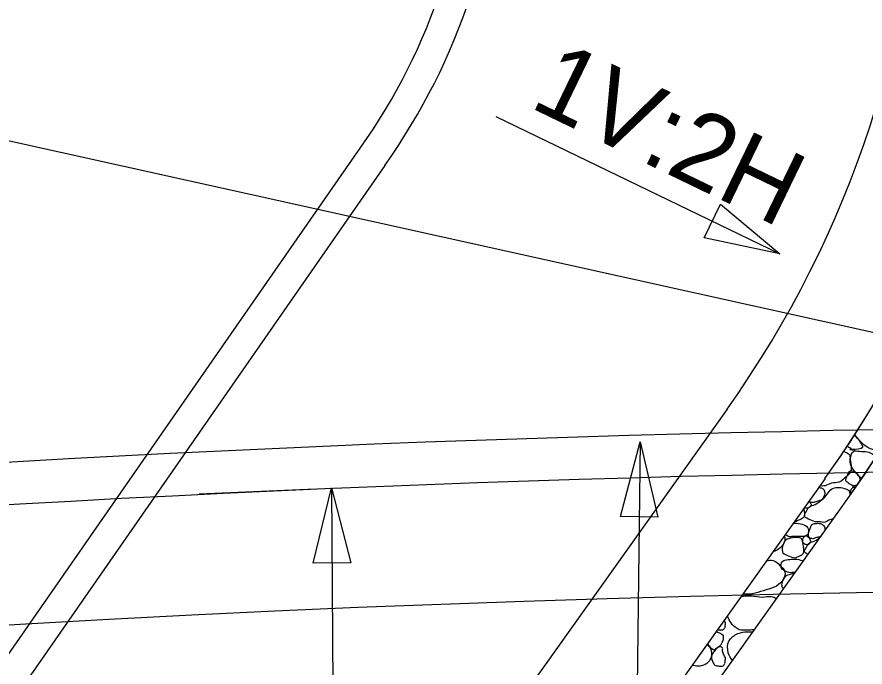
# Model space of a CAD drawing. Extents: x 1385284 to 1385995, y 1975154 to 1975620.
# Drawn here: x 1385473.66 to 1385501.91, y 1975497.97 to 1975519.64 of the extents above; entities that cross this region are included whole.
import ezdxf

# ---------------------------------------------------------------- set-up
doc = ezdxf.new("R2010")
doc.units = 0
for name, color, linetype in [('Default', 7, 'Continuous'), ('R_Bridge', 7, 'Continuous'), ('R_Horz Alg Annot', 7, 'Continuous'), ('R_Proposed Const Limits', 7, 'Continuous'), ('R_Proposed Road', 7, 'Continuous')]:
    doc.layers.add(name, color=color, linetype=linetype)

msp = doc.modelspace()

# ---------------------------------------------------------------- linework, layer by layer
at = {"layer": 'Default'}
for p, q in [((1385489.616, 1975516.319), (1385499.073, 1975511.745)), ((1385459.222, 1975478.038), (1385485.092, 1975515.258)), ((1385485.913, 1975514.687), (1385460.044, 1975477.467)), ((1385494.416, 1975505.475), (1385494.049, 1975472.644)), ((1385500.579, 1975504.251), (1385472.911, 1975465.371)), ((1385483.611, 1975503.895), (1385479.734, 1975503.734)), ((1385484.136, 1975503.942), (1385484.353, 1975473.943)), ((1385473.726, 1975464.791), (1385501.394, 1975503.671))]:
    msp.add_line(p, q, dxfattribs=at)
for points in [[(1385497.095, 1975513.396), (1385499.073, 1975511.745), (1385496.551, 1975512.271)], [(1385493.763, 1975502.983), (1385494.416, 1975505.475), (1385495.013, 1975502.969)], [(1385483.529, 1975501.438), (1385484.136, 1975503.942), (1385484.779, 1975501.447)]]:
    msp.add_lwpolyline(points, close=True, dxfattribs=at)
for radius, end in [(40, 101.9984), (39, 101.9984), (40, 46.1158), (39, 45.8751), (21, 101.9984), (20, 101.9984)]:
    msp.add_arc((1385468.803, 1975526.863), radius, 324.5634, end, dxfattribs=at)
for points in [[(1385501.542, 1975505.711), (1385501.59, 1975505.684), (1385501.684, 1975505.595), (1385501.749, 1975505.454), (1385501.936, 1975505.205), (1385501.187, 1975505.222), (1385501.573, 1975505.212), (1385501.565, 1975505.214)], [(1385502.213, 1975505.214), (1385502.142, 1975505.211), (1385501.96, 1975505.295), (1385501.763, 1975505.477), (1385501.628, 1975505.63), (1385501.558, 1975505.726), (1385501.555, 1975505.73)], [(1385501.175, 1975505.155), (1385501.185, 1975505.154), (1385501.247, 1975505.144), (1385501.42, 1975505.063), (1385501.412, 1975504.835), (1385501.498, 1975504.524), (1385501.284, 1975504.317), (1385501.062, 1975504.095), (1385500.786, 1975504.127), (1385500.577, 1975503.984), (1385500.459, 1975504.006), (1385500.409, 1975504.012)], [(1385501.531, 1975505.214), (1385501.484, 1975505.213), (1385501.404, 1975505.273), (1385501.326, 1975505.327), (1385501.304, 1975505.351)], [(1385501.783, 1975504.262), (1385501.783, 1975504.262), (1385501.703, 1975504.342), (1385501.552, 1975504.498), (1385501.394, 1975504.738), (1385501.426, 1975504.964), (1385501.497, 1975505.206), (1385501.726, 1975505.154), (1385501.996, 1975505.159), (1385502.179, 1975505.065), (1385502.266, 1975505.01), (1385502.274, 1975505.006)], [(1385501.531, 1975504.011), (1385501.484, 1975504.01), (1385501.388, 1975504.083), (1385501.225, 1975504.176), (1385501.334, 1975504.361), (1385501.382, 1975504.526), (1385501.563, 1975504.5), (1385501.682, 1975504.395), (1385501.724, 1975504.28), (1385501.748, 1975504.216), (1385501.75, 1975504.211)], [(1385501.623, 1975504.018), (1385501.577, 1975504.015), (1385501.4, 1975504.013), (1385501.573, 1975504.009), (1385501.565, 1975504.011)], [(1385500.305, 1975502.808), (1385500.233, 1975502.803), (1385500.098, 1975502.883), (1385499.838, 1975502.973), (1385499.952, 1975503.141), (1385500.031, 1975503.328), (1385500.256, 1975503.373), (1385500.456, 1975503.531), (1385500.635, 1975503.673), (1385500.73, 1975503.879), (1385500.942, 1975503.972), (1385501.157, 1975503.946), (1385501.393, 1975503.879), (1385501.406, 1975503.765), (1385501.413, 1975503.701)], [(1385500.371, 1975503.959), (1385500.409, 1975503.955), (1385500.494, 1975503.936), (1385500.585, 1975503.835), (1385500.561, 1975503.675), (1385500.5, 1975503.558), (1385500.447, 1975503.528)], [(1385501.412, 1975503.699), (1385501.414, 1975503.726), (1385501.43, 1975503.81), (1385501.468, 1975503.958), (1385501.559, 1975503.967), (1385501.588, 1975503.965)], [(1385500.042, 1975503.497), (1385500.045, 1975503.495), (1385500.094, 1975503.454), (1385500.141, 1975503.351), (1385500.053, 1975503.291), (1385500.02, 1975503.262)], [(1385500.447, 1975503.528), (1385500.4, 1975503.513), (1385500.304, 1975503.49), (1385500.169, 1975503.436), (1385500.081, 1975503.461), (1385500.045, 1975503.495), (1385500.043, 1975503.497)], [(1385499.867, 1975503.25), (1385499.868, 1975503.247), (1385499.891, 1975503.157), (1385499.917, 1975502.958), (1385499.732, 1975502.881), (1385499.629, 1975502.833), (1385499.581, 1975502.808)], [(1385500.02, 1975503.262), (1385499.982, 1975503.262), (1385499.937, 1975503.261), (1385499.896, 1975503.282), (1385499.891, 1975503.285)], [(1385500.846, 1975502.901), (1385500.808, 1975502.896), (1385500.709, 1975502.88), (1385500.549, 1975502.749), (1385500.384, 1975502.828), (1385500.305, 1975502.808)], [(1385499.52, 1975502.763), (1385499.588, 1975502.763), (1385499.762, 1975502.762), (1385499.998, 1975502.669), (1385500.057, 1975502.483), (1385499.962, 1975502.317), (1385499.756, 1975502.324), (1385499.596, 1975502.319), (1385499.476, 1975502.325)], [(1385499.581, 1975502.808), (1385499.572, 1975502.809), (1385499.564, 1975502.811), (1385499.555, 1975502.813)], [(1385500.433, 1975502.321), (1385500.39, 1975502.308), (1385500.299, 1975502.286), (1385500.169, 1975502.233), (1385500.043, 1975502.275), (1385500.015, 1975502.382), (1385500.046, 1975502.495), (1385500.089, 1975502.622), (1385500.15, 1975502.747), (1385500.3, 1975502.763), (1385500.472, 1975502.759), (1385500.572, 1975502.645), (1385500.58, 1975502.56), (1385500.572, 1975502.516)], [(1385499.226, 1975502.349), (1385499.272, 1975502.243), (1385499.18, 1975502.008), (1385498.995, 1975501.865), (1385498.883, 1975501.822), (1385498.839, 1975501.806)], [(1385499.476, 1975502.325), (1385499.421, 1975502.301), (1385499.333, 1975502.337), (1385499.263, 1975502.374), (1385499.249, 1975502.382)], [(1385500.02, 1975502.059), (1385499.982, 1975502.059), (1385499.898, 1975502.057), (1385499.818, 1975502.139), (1385499.826, 1975502.257), (1385499.91, 1975502.359), (1385500.038, 1975502.309), (1385500.141, 1975502.148), (1385500.053, 1975502.088), (1385500.02, 1975502.059)], [(1385499.581, 1975501.605), (1385499.509, 1975501.615), (1385499.365, 1975501.685), (1385499.141, 1975501.755), (1385499.144, 1975501.983), (1385499.254, 1975502.229), (1385499.47, 1975502.278), (1385499.832, 1975502.308), (1385499.835, 1975502.066), (1385499.917, 1975501.755), (1385499.732, 1975501.678), (1385499.629, 1975501.63), (1385499.581, 1975501.605)], [(1385500.006, 1975501.721), (1385499.961, 1975501.747), (1385499.859, 1975501.8), (1385499.952, 1975501.938), (1385500.031, 1975502.125), (1385500.245, 1975502.161), (1385500.368, 1975502.255), (1385500.416, 1975502.297)], [(1385498.635, 1975501.519), (1385498.698, 1975501.521), (1385498.867, 1975501.56), (1385499.056, 1975501.372), (1385499.308, 1975501.168), (1385499.182, 1975500.808), (1385498.894, 1975500.617), (1385498.525, 1975500.517), (1385498.154, 1975500.388), (1385497.921, 1975500.403), (1385497.849, 1975500.406)], [(1385499.476, 1975501.122), (1385499.421, 1975501.098), (1385499.276, 1975501.156), (1385499.114, 1975501.242), (1385499.104, 1975501.409), (1385499.18, 1975501.541), (1385499.4, 1975501.559), (1385499.638, 1975501.578), (1385499.812, 1975501.526), (1385499.853, 1975501.506)], [(1385499.192, 1975500.577), (1385499.19, 1975500.579), (1385499.14, 1975500.631), (1385499.144, 1975500.78), (1385499.254, 1975501.026), (1385499.425, 1975501.066), (1385499.54, 1975501.104), (1385499.572, 1975501.112)], [(1385499.578, 1975501.119), (1385499.544, 1975501.119), (1385499.51, 1975501.12), (1385499.476, 1975501.122)], [(1385497.786, 1975500.326), (1385497.879, 1975500.346), (1385498.141, 1975500.352), (1385498.486, 1975500.281), (1385498.806, 1975500.355), (1385498.917, 1975500.282), (1385498.957, 1975500.247)], [(1385497.849, 1975500.406), (1385497.846, 1975500.405), (1385497.843, 1975500.403), (1385497.84, 1975500.402)], [(1385497.219, 1975499.53), (1385497.23, 1975499.491), (1385497.285, 1975499.426), (1385497.229, 1975499.334), (1385497.248, 1975499.304)], [(1385497.849, 1975499.203), (1385497.781, 1975499.169), (1385497.558, 1975499.306), (1385497.415, 1975499.48), (1385497.343, 1975499.639), (1385497.328, 1975499.683)], [(1385497.248, 1975499.304), (1385497.238, 1975499.279), (1385497.19, 1975499.189), (1385497.089, 1975499.202), (1385497.014, 1975499.198), (1385496.987, 1975499.203)], [(1385498.227, 1975499.222), (1385498.174, 1975499.21), (1385498.048, 1975499.192), (1385497.921, 1975499.2), (1385497.849, 1975499.203)], [(1385496.947, 1975499.147), (1385496.974, 1975499.145), (1385497.068, 1975499.121), (1385497.215, 1975499.031), (1385497.164, 1975498.793), (1385497.051, 1975498.628), (1385496.947, 1975498.581), (1385496.922, 1975498.57)], [(1385497.496, 1975498.194), (1385497.453, 1975498.244), (1385497.326, 1975498.413), (1385497.313, 1975498.866), (1385497.69, 1975499.122), (1385497.993, 1975499.152), (1385498.136, 1975499.144), (1385498.17, 1975499.142)], [(1385496.663, 1975498.749), (1385496.729, 1975498.659), (1385496.821, 1975498.512), (1385496.783, 1975498.212), (1385496.597, 1975498.04), (1385496.429, 1975497.996), (1385496.344, 1975497.996)], [(1385496.922, 1975498.57), (1385496.89, 1975498.496), (1385496.738, 1975498.629), (1385496.672, 1975498.721), (1385496.659, 1975498.743)], [(1385497.248, 1975498.101), (1385497.238, 1975498.076), (1385497.19, 1975497.986), (1385497.067, 1975498.001), (1385496.889, 1975498.02), (1385496.851, 1975498.136), (1385496.777, 1975498.245), (1385496.815, 1975498.409), (1385496.91, 1975498.521), (1385496.987, 1975498.609), (1385497.067, 1975498.665), (1385497.192, 1975498.614), (1385497.149, 1975498.497), (1385497.211, 1975498.371), (1385497.293, 1975498.235), (1385497.229, 1975498.131), (1385497.248, 1975498.101)], [(1385496.344, 1975497.996), (1385496.284, 1975497.993), (1385496.224, 1975498.015), (1385496.164, 1975498.048)]]:
    msp.add_open_spline(points, degree=3, dxfattribs=at)
at = {"layer": 'R_Bridge'}
for radius in [710.911, 709.494]:
    msp.add_arc((1385514.357, 1974795.066), radius, 84.79144, 93.554346, dxfattribs=at)
at = {"layer": 'R_Horz Alg Annot'}
msp.add_line((1385315.54, 1975550.51), (1385664.693, 1975473.094), dxfattribs=at)
at = {"layer": 'R_Proposed Const Limits'}
msp.add_line((1385497.32, 1975506.57), (1385469.652, 1975467.69), dxfattribs=at)
msp.add_arc((1385468.803, 1975526.863), 35, 324.5634, 101.9984, dxfattribs=at)
at = {"layer": 'R_Proposed Road'}
msp.add_arc((1385514.357, 1974795.066), 705.494, 77.498258, 106.368381, dxfattribs=at)

# ---------------------------------------------------------------- texts
at = {"layer": 'Default'}
msp.add_text('1V:2H', height=2.5, rotation=334.1902, dxfattribs=at).set_placement((1385490.689, 1975516.649))

doc.saveas('drawing.dxf')
